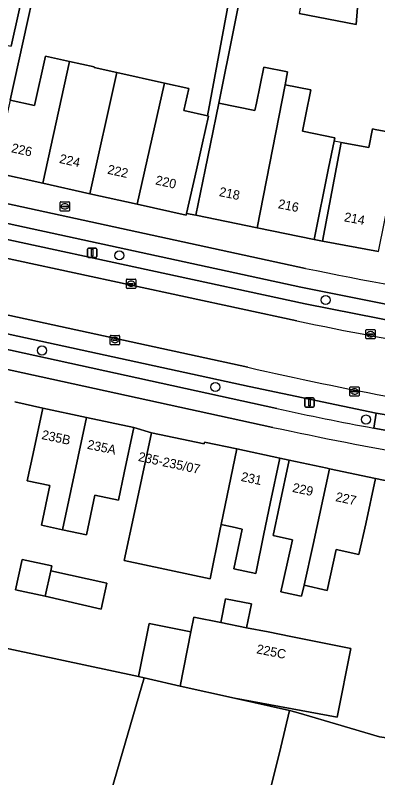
# Model space of a CAD drawing. Extents: x 158086 to 159499, y 382904 to 383981.
# Drawn here: x 158278.9 to 158318, y 383140.7 to 383222.9 of the extents above; entities that cross this region are included whole.
import ezdxf

# ---------------------------------------------------------------- set-up
doc = ezdxf.new("R2010")
doc.units = 0
for name, color, linetype in [('IMGEO_Berm_open', 7, 'Continuous'), ('IMGEO_Boom', 7, 'Continuous'), ('IMGEO_Brandkraan', 7, 'Continuous'), ('IMGEO_Erf', 7, 'Continuous'), ('IMGEO_Fietspad_gesloten', 7, 'Continuous'), ('IMGEO_Kolk', 7, 'Continuous'), ('IMGEO_Lichtmast', 7, 'Continuous'), ('IMGEO_Pand', 7, 'Continuous'), ('IMGEO_Pand_nummerreeks', 7, 'Continuous'), ('IMGEO_Pand_overbouw', 7, 'Continuous'), ('IMGEO_Parkeervlak_open', 7, 'Continuous'), ('IMGEO_Rijbaan_lokaal_gesloten', 7, 'Continuous'), ('IMGEO_Voetpad_open', 7, 'Continuous')]:
    doc.layers.add(name, color=color, linetype=linetype)

msp = doc.modelspace()

# ---------------------------------------------------------------- linework, layer by layer
at = {"layer": 'IMGEO_Berm_open'}
for points in [[(158276.869, 383198.965), (158310.165, 383191.768), (158320.914, 383189.662), (158321.216, 383191.287), (158309.726, 383193.572), (158241.35, 383208.396), (158202.859, 383217.005), (158187.053, 383220.294)], [(158254.9, 383193.55), (158236.292, 383197.608), (158201.626, 383205.353), (158201.292, 383203.669), (158307.14, 383180.487)], [(158304.134, 383182.846), (158274.722, 383189.241)], [(158317.563, 383178.385), (158317.844, 383179.993), (158304.134, 383182.846)]]:
    msp.add_lwpolyline(points, dxfattribs=at)
msp.add_arc((158363.133, 383431.241), 256.929, 257.41247, 259.78379, dxfattribs=at)
at = {"layer": 'IMGEO_Boom'}
for centre in [(158290.149, 383196.988), (158312.381, 383192.178), (158281.81, 383186.743), (158300.492, 383182.804), (158316.724, 383179.303)]:
    msp.add_circle(centre, 0.489, dxfattribs=at)
at = {"layer": 'IMGEO_Brandkraan'}
for p, q in [((158283.773, 383201.849), (158283.773, 383202.701)), ((158283.848, 383202.775), (158284.7, 383202.775)), ((158284.261, 383202.555), (158284.286, 383202.555)), ((158284.774, 383202.701), (158284.774, 383201.849)), ((158284.7, 383201.775), (158283.848, 383201.775)), ((158284.032, 383202.269), (158284.032, 383202.281)), ((158284.47, 383202.232), (158284.072, 383202.232)), ((158284.075, 383202.318), (158284.473, 383202.318)), ((158284.284, 383201.995), (158284.259, 383201.995)), ((158284.516, 383202.281), (158284.516, 383202.269))]:
    msp.add_line(p, q, dxfattribs=at)
for points in [[(158283.773, 383201.849), (158283.773, 383202.701)], [(158283.848, 383202.775), (158284.7, 383202.775)], [(158284.774, 383202.701), (158284.774, 383201.849)], [(158284.7, 383201.775), (158283.848, 383201.775)]]:
    msp.add_lwpolyline(points, dxfattribs=at)
for centre, radius, start, end in [((158283.85, 383202.699), 0.0765, 91.55205, 178.44795), ((158283.85, 383202.699), 0.0765, 91.55205, 178.44795), ((158284.698, 383202.699), 0.0765, 1.55205, 88.44795), ((158284.698, 383202.699), 0.0765, 1.55205, 88.44795), ((158283.85, 383201.851), 0.0765, 181.55205, 268.44795), ((158283.85, 383201.851), 0.0765, 181.55205, 268.44795), ((158284.072, 383202.278), 0.0403, 85.87752, 175.75265), ((158284.069, 383202.268), 0.0366, 178.93798, 274.71019), ((158284.473, 383202.275), 0.043, 264.86636, 352.45326), ((158284.477, 383202.28), 0.0386, 1.73085, 96.63898), ((158284.698, 383201.851), 0.0765, 271.55205, 358.44795), ((158284.698, 383201.851), 0.0765, 271.55205, 358.44795)]:
    msp.add_arc(centre, radius, start, end, dxfattribs=at)
for centre, major_axis, ratio, start_param, end_param in [((158284.26, 383202.275), (-0.387, 0.002), 0.722429, 4.712389, 7.853982), ((158284.285, 383202.275), (-0.39, 0.002), 0.717154, 1.570796, 4.712389)]:
    msp.add_ellipse(centre, major_axis=major_axis, ratio=ratio, start_param=start_param, end_param=end_param, dxfattribs=at)
at = {"layer": 'IMGEO_Erf'}
for points in [[(158283.383, 383241.47), (158276.191, 383243.15), (158275.131, 383238.484), (158270.865, 383239.454), (158270.731, 383238.86), (158264.911, 383240.184), (158260.691, 383221.367), (158263.775, 383220.678), (158265.351, 383227.737), (158267.873, 383227.174), (158267.293, 383224.576), (158269.747, 383224.028), (158269.199, 383221.573), (158267.997, 383216.19), (158271.563, 383215.394), (158272.77, 383220.82), (158278.489, 383219.543)], [(158303.246, 383231.413), (158298.621, 383232.637), (158298.105, 383230.685), (158293.201, 383231.983), (158293.24, 383232.149), (158288.16, 383233.26), (158287.893, 383232.039), (158282.666, 383233.182), (158278.387, 383213.724), (158281.013, 383213.138), (158282.206, 383218.481), (158284.791, 383217.904), (158287.429, 383217.315), (158287.418, 383217.261), (158289.866, 383216.714), (158295.004, 383215.566), (158297.637, 383214.977), (158297.109, 383212.609), (158299.661, 383212.039)], [(158282.865, 383163.519), (158282.749, 383162.993), (158288.817, 383161.655), (158288.197, 383158.842), (158282.146, 383160.259), (158278.959, 383160.961), (158279.678, 383164.222)]]:
    msp.add_lwpolyline(points, close=True, dxfattribs=at)
for points in [[(158316.527, 383232.939), (158315.687, 383221.879), (158309.526, 383223.074)], [(158304.128, 383229.734), (158300.88, 383213.391), (158304.765, 383212.596), (158304.927, 383213.388), (158305.728, 383217.298), (158308.277, 383216.776), (158308.009, 383215.395), (158310.801, 383214.823), (158310.262, 383212.193), (158309.888, 383210.368), (158313.372, 383209.654), (158313.302, 383209.314), (158312.706, 383206.404), (158311.132, 383198.719), (158312.044, 383198.541), (158314.046, 383209.174), (158317.047, 383208.608), (158317.427, 383210.63), (158317.709, 383210.577), (158320.635, 383210.026)], [(158322.217, 383172.026), (158317.747, 383172.943), (158316.704, 383168.053), (158315.955, 383164.754), (158313.526, 383165.288), (158312.556, 383160.881), (158310.053, 383161.432), (158309.793, 383160.248), (158309.561, 383160.299), (158307.566, 383160.738), (158307.807, 383161.835), (158308.797, 383166.329), (158306.711, 383166.788), (158307.404, 383170.036), (158308.447, 383174.926), (158307.439, 383175.141), (158306.396, 383170.252), (158305.738, 383166.996), (158304.849, 383162.702), (158302.48, 383163.207), (158303.395, 383167.499), (158302.324, 383167.727), (158301.254, 383167.955), (158301.132, 383167.981), (158300.995, 383167.31), (158299.938, 383162.145), (158290.677, 383164.118), (158291.78, 383169.292), (158292.569, 383172.995), (158293.612, 383177.885), (158291.71, 383178.432), (158290.668, 383173.542), (158290.043, 383170.612), (158287.507, 383171.153), (158286.596, 383166.878), (158284.04, 383167.423), (158281.758, 383167.91), (158282.669, 383172.18), (158280.23, 383172.701), (158280.856, 383175.635), (158281.898, 383180.525), (158278.879, 383181.201)], [(158272.796, 383155.743), (158292.196, 383151.584), (158293.362, 383157.32), (158297.853, 383156.407), (158298.171, 383158.005), (158301.092, 383157.42), (158301.606, 383159.987), (158304.376, 383159.432), (158303.861, 383156.865), (158306.179, 383156.4), (158308.629, 383155.909), (158315.091, 383154.614), (158313.609, 383147.219), (158302.551, 383149.261), (158308.489, 383147.926), (158309.179, 383147.771), (158310.039, 383147.519), (158313.464, 383146.515), (158318.204, 383145.101), (158345.406, 383141.19), (158345.597, 383141.163), (158347.51, 383148.249), (158355.692, 383146.915), (158351.159, 383130.728)]]:
    msp.add_lwpolyline(points, dxfattribs=at)
at = {"layer": 'IMGEO_Fietspad_gesloten'}
for points in [[(158310.224, 383195.595), (158241.603, 383210.483), (158207.946, 383218.002), (158195.608, 383220.653), (158184.729, 383222.86)], [(158187.053, 383220.294), (158202.859, 383217.005), (158241.35, 383208.396), (158309.726, 383193.572), (158321.216, 383191.287), (158327.206, 383190.282)], [(158138.36, 383212.086), (158139.992, 383211.926), (158163.458, 383208.795), (158169.284, 383207.897), (158174.364, 383207.03), (158187.059, 383204.599), (158306.699, 383178.457)], [(158307.14, 383180.487), (158201.292, 383203.669), (158197.351, 383204.538), (158190.588, 383205.987)], [(158323.581, 383177.291), (158317.563, 383178.385)]]:
    msp.add_lwpolyline(points, dxfattribs=at)
for centre, radius, start, end in [((158417.115, 383717.399), 532.64, 258.42313, 262.61206), ((158363.133, 383431.241), 256.929, 257.41247, 259.78379), ((158394.655, 383587.161), 418.061, 257.85472, 262.24316)]:
    msp.add_arc(centre, radius, start, end, dxfattribs=at)
at = {"layer": 'IMGEO_Kolk'}
for p, q in [((158290.913, 383193.513), (158290.913, 383194.365)), ((158290.988, 383194.439), (158291.84, 383194.439)), ((158291.914, 383194.365), (158291.914, 383193.513)), ((158291.172, 383193.933), (158291.172, 383193.945)), ((158291.61, 383193.896), (158291.212, 383193.896)), ((158291.215, 383193.982), (158291.613, 383193.982)), ((158291.424, 383193.659), (158291.399, 383193.659)), ((158291.401, 383194.219), (158291.426, 383194.219)), ((158291.656, 383193.945), (158291.656, 383193.933)), ((158291.84, 383193.439), (158290.988, 383193.439)), ((158316.718, 383188.07), (158316.718, 383188.922)), ((158316.793, 383188.996), (158317.645, 383188.996)), ((158317.206, 383188.776), (158317.231, 383188.776)), ((158317.719, 383188.922), (158317.719, 383188.07)), ((158289.177, 383187.44), (158289.177, 383188.292)), ((158289.252, 383188.366), (158290.104, 383188.366)), ((158289.436, 383187.86), (158289.436, 383187.872)), ((158289.874, 383187.823), (158289.476, 383187.823)), ((158289.479, 383187.909), (158289.877, 383187.909)), ((158289.665, 383188.146), (158289.69, 383188.146)), ((158289.92, 383187.872), (158289.92, 383187.86)), ((158290.178, 383188.292), (158290.178, 383187.44)), ((158317.645, 383187.996), (158316.793, 383187.996)), ((158316.977, 383188.49), (158316.977, 383188.502)), ((158317.415, 383188.453), (158317.017, 383188.453)), ((158317.02, 383188.539), (158317.418, 383188.539)), ((158317.229, 383188.216), (158317.204, 383188.216)), ((158317.461, 383188.502), (158317.461, 383188.49)), ((158290.104, 383187.366), (158289.252, 383187.366)), ((158289.688, 383187.586), (158289.663, 383187.586)), ((158315.066, 383182.823), (158315.918, 383182.823)), ((158314.991, 383181.897), (158314.991, 383182.749)), ((158315.25, 383182.317), (158315.25, 383182.329)), ((158315.688, 383182.28), (158315.29, 383182.28)), ((158315.293, 383182.366), (158315.691, 383182.366)), ((158315.502, 383182.043), (158315.477, 383182.043)), ((158315.479, 383182.603), (158315.504, 383182.603)), ((158315.734, 383182.329), (158315.734, 383182.317)), ((158315.992, 383182.749), (158315.992, 383181.897)), ((158315.918, 383181.823), (158315.066, 383181.823))]:
    msp.add_line(p, q, dxfattribs=at)
for points in [[(158290.913, 383193.513), (158290.913, 383194.365)], [(158290.988, 383194.439), (158291.84, 383194.439)], [(158291.914, 383194.365), (158291.914, 383193.513)], [(158291.84, 383193.439), (158290.988, 383193.439)], [(158316.718, 383188.07), (158316.718, 383188.922)], [(158316.793, 383188.996), (158317.645, 383188.996)], [(158317.719, 383188.922), (158317.719, 383188.07)], [(158289.177, 383187.44), (158289.177, 383188.292)], [(158289.252, 383188.366), (158290.104, 383188.366)], [(158290.178, 383188.292), (158290.178, 383187.44)], [(158317.645, 383187.996), (158316.793, 383187.996)], [(158290.104, 383187.366), (158289.252, 383187.366)], [(158315.066, 383182.823), (158315.918, 383182.823)], [(158314.991, 383181.897), (158314.991, 383182.749)], [(158315.992, 383182.749), (158315.992, 383181.897)], [(158315.918, 383181.823), (158315.066, 383181.823)]]:
    msp.add_lwpolyline(points, dxfattribs=at)
for centre, radius, start, end in [((158290.99, 383194.363), 0.0765, 91.55205, 178.44795), ((158290.99, 383194.363), 0.0765, 91.55205, 178.44795), ((158291.838, 383194.363), 0.0765, 1.55205, 88.44795), ((158291.838, 383194.363), 0.0765, 1.55205, 88.44795), ((158290.99, 383193.515), 0.0765, 181.55205, 268.44795), ((158290.99, 383193.515), 0.0765, 181.55205, 268.44795), ((158291.212, 383193.942), 0.0403, 85.87752, 175.75265), ((158291.209, 383193.932), 0.0366, 178.93798, 274.71019), ((158291.613, 383193.939), 0.043, 264.86636, 352.45326), ((158291.617, 383193.944), 0.0386, 1.73085, 96.63898), ((158291.838, 383193.515), 0.0765, 271.55205, 358.44795), ((158291.838, 383193.515), 0.0765, 271.55205, 358.44795), ((158316.795, 383188.92), 0.0765, 91.55205, 178.44795), ((158316.795, 383188.92), 0.0765, 91.55205, 178.44795), ((158317.643, 383188.92), 0.0765, 1.55205, 88.44795), ((158317.643, 383188.92), 0.0765, 1.55205, 88.44795), ((158289.254, 383188.29), 0.0765, 91.55205, 178.44795), ((158289.254, 383188.29), 0.0765, 91.55205, 178.44795), ((158289.476, 383187.869), 0.0403, 85.87752, 175.75265), ((158289.473, 383187.859), 0.0366, 178.93798, 274.71019), ((158289.877, 383187.866), 0.043, 264.86636, 352.45326), ((158289.881, 383187.871), 0.0386, 1.73085, 96.63898), ((158290.102, 383188.29), 0.0765, 1.55205, 88.44795), ((158290.102, 383188.29), 0.0765, 1.55205, 88.44795), ((158316.795, 383188.072), 0.0765, 181.55205, 268.44795), ((158316.795, 383188.072), 0.0765, 181.55205, 268.44795), ((158317.017, 383188.499), 0.0403, 85.87752, 175.75265), ((158317.014, 383188.489), 0.0366, 178.93798, 274.71019), ((158317.418, 383188.496), 0.043, 264.86636, 352.45326), ((158317.422, 383188.501), 0.0386, 1.73085, 96.63898), ((158317.643, 383188.072), 0.0765, 271.55205, 358.44795), ((158317.643, 383188.072), 0.0765, 271.55205, 358.44795), ((158289.254, 383187.442), 0.0765, 181.55205, 268.44795), ((158289.254, 383187.442), 0.0765, 181.55205, 268.44795), ((158290.102, 383187.442), 0.0765, 271.55205, 358.44795), ((158290.102, 383187.442), 0.0765, 271.55205, 358.44795), ((158315.068, 383182.747), 0.0765, 91.55205, 178.44795), ((158315.068, 383182.747), 0.0765, 91.55205, 178.44795), ((158315.916, 383182.747), 0.0765, 1.55205, 88.44795), ((158315.916, 383182.747), 0.0765, 1.55205, 88.44795), ((158315.29, 383182.326), 0.0403, 85.87752, 175.75265), ((158315.287, 383182.316), 0.0366, 178.93798, 274.71019), ((158315.691, 383182.323), 0.043, 264.86636, 352.45326), ((158315.695, 383182.328), 0.0386, 1.73085, 96.63898), ((158315.068, 383181.899), 0.0765, 181.55205, 268.44795), ((158315.068, 383181.899), 0.0765, 181.55205, 268.44795), ((158315.916, 383181.899), 0.0765, 271.55205, 358.44795), ((158315.916, 383181.899), 0.0765, 271.55205, 358.44795)]:
    msp.add_arc(centre, radius, start, end, dxfattribs=at)
for centre, major_axis, ratio, start_param, end_param in [((158291.4, 383193.939), (-0.387, 0.002), 0.722429, 4.712389, 7.853982), ((158291.425, 383193.939), (-0.39, 0.002), 0.717154, 1.570796, 4.712389), ((158317.205, 383188.496), (-0.387, 0.002), 0.722429, 4.712389, 7.853982), ((158317.23, 383188.496), (-0.39, 0.002), 0.717154, 1.570796, 4.712389), ((158289.664, 383187.866), (-0.387, 0.002), 0.722429, 4.712389, 7.853982), ((158289.689, 383187.866), (-0.39, 0.002), 0.717154, 1.570796, 4.712389), ((158315.478, 383182.323), (-0.387, 0.002), 0.722429, 4.712389, 7.853982), ((158315.503, 383182.323), (-0.39, 0.002), 0.717154, 1.570796, 4.712389)]:
    msp.add_ellipse(centre, major_axis=major_axis, ratio=ratio, start_param=start_param, end_param=end_param, dxfattribs=at)
at = {"layer": 'IMGEO_Lichtmast'}
for p, q in [((158286.723, 383196.876), (158286.723, 383197.676)), ((158286.723, 383197.676), (158286.723, 383196.876)), ((158286.823, 383197.776), (158287.613, 383197.776)), ((158287.613, 383197.776), (158286.823, 383197.776)), ((158287.713, 383197.676), (158287.713, 383196.876)), ((158287.713, 383196.876), (158287.713, 383197.676)), ((158287.613, 383196.776), (158286.823, 383196.776)), ((158286.823, 383196.776), (158287.613, 383196.776)), ((158310.14, 383180.745), (158310.14, 383181.545)), ((158310.14, 383181.545), (158310.14, 383180.745)), ((158310.24, 383181.645), (158311.03, 383181.645)), ((158311.03, 383181.645), (158310.24, 383181.645)), ((158311.13, 383181.545), (158311.13, 383180.745)), ((158311.13, 383180.745), (158311.13, 383181.545)), ((158311.03, 383180.645), (158310.24, 383180.645)), ((158310.24, 383180.645), (158311.03, 383180.645))]:
    msp.add_line(p, q, dxfattribs=at)
for points in [[(158287.143, 383197.651), (158287.293, 383197.651), (158287.293, 383196.901), (158287.143, 383196.901), (158287.143, 383197.651)], [(158310.56, 383181.52), (158310.71, 383181.52), (158310.71, 383180.77), (158310.56, 383180.77), (158310.56, 383181.52)]]:
    msp.add_lwpolyline(points, dxfattribs=at)
for centre, start, end in [((158286.823, 383197.676), 90, 180), ((158286.823, 383197.676), 90, 180), ((158287.613, 383197.676), 0, 90), ((158287.613, 383197.676), 360, 90), ((158286.823, 383196.876), 180, 270), ((158286.823, 383196.876), 180, 270), ((158287.613, 383196.876), 270, 0), ((158287.613, 383196.876), 270, 0), ((158310.24, 383181.545), 90, 180), ((158310.24, 383181.545), 90, 180), ((158311.03, 383181.545), 0, 90), ((158311.03, 383181.545), 360, 90), ((158310.24, 383180.745), 180, 270), ((158310.24, 383180.745), 180, 270), ((158311.03, 383180.745), 270, 0), ((158311.03, 383180.745), 270, 0)]:
    msp.add_arc(centre, 0.1, start, end, dxfattribs=at)
at = {"layer": 'IMGEO_Pand'}
for points in [[(158316.527, 383232.939), (158311.633, 383234.07), (158310.525, 383228.36), (158309.526, 383223.074), (158315.687, 383221.879)], [(158284.791, 383217.904), (158282.206, 383218.481), (158281.013, 383213.138), (158278.387, 383213.724), (158277.74, 383210.824), (158276.65, 383205.944), (158281.908, 383204.77)], [(158289.866, 383216.714), (158287.418, 383217.261), (158287.429, 383217.315), (158284.791, 383217.904), (158281.908, 383204.77), (158286.976, 383203.639)], [(158295.004, 383215.566), (158289.866, 383216.714), (158286.976, 383203.639), (158292.066, 383202.503), (158294.967, 383215.402)], [(158308.009, 383215.395), (158308.277, 383216.776), (158305.728, 383217.298), (158304.927, 383213.388), (158304.765, 383212.596), (158300.88, 383213.391), (158299.985, 383209.022), (158299.412, 383206.225), (158298.408, 383201.326), (158305.016, 383199.972)], [(158299.1, 383209.119), (158299.747, 383212.02), (158299.661, 383212.039), (158297.109, 383212.609), (158297.637, 383214.977), (158295.004, 383215.566), (158294.967, 383215.402), (158292.066, 383202.503), (158297.359, 383201.321), (158297.405, 383201.528), (158298.449, 383206.201)], [(158313.302, 383209.314), (158313.372, 383209.654), (158309.888, 383210.368), (158310.262, 383212.193), (158310.801, 383214.823), (158308.009, 383215.395), (158305.016, 383199.972), (158311.132, 383198.719), (158312.706, 383206.404)], [(158320.635, 383210.026), (158317.709, 383210.577), (158317.427, 383210.63), (158317.047, 383208.608), (158314.046, 383209.174), (158312.044, 383198.541), (158318.089, 383197.403)], [(158284.04, 383167.423), (158286.621, 383179.518), (158281.898, 383180.525), (158280.856, 383175.635), (158280.23, 383172.701), (158282.669, 383172.18), (158281.758, 383167.91)], [(158284.04, 383167.423), (158286.596, 383166.878), (158287.507, 383171.153), (158290.043, 383170.612), (158290.668, 383173.542), (158291.71, 383178.432), (158286.621, 383179.518)], [(158302.8, 383176.13), (158299.321, 383176.872), (158299.279, 383176.676), (158293.612, 383177.885), (158292.569, 383172.995), (158291.78, 383169.292), (158290.677, 383164.118), (158299.938, 383162.145), (158300.995, 383167.31), (158301.132, 383167.981)], [(158307.439, 383175.141), (158302.8, 383176.13), (158301.132, 383167.981), (158301.254, 383167.955), (158302.324, 383167.727), (158303.395, 383167.499), (158302.48, 383163.207), (158304.849, 383162.702), (158305.738, 383166.996), (158306.396, 383170.252)], [(158312.818, 383173.994), (158312.553, 383174.05), (158308.447, 383174.926), (158307.404, 383170.036), (158306.711, 383166.788), (158308.797, 383166.329), (158307.807, 383161.835), (158307.566, 383160.738), (158309.561, 383160.299), (158309.793, 383160.248), (158310.053, 383161.432), (158311.023, 383165.839)], [(158317.747, 383172.943), (158312.818, 383173.994), (158311.023, 383165.839), (158310.053, 383161.432), (158312.556, 383160.881), (158313.526, 383165.288), (158315.955, 383164.754), (158316.704, 383168.053)], [(158282.749, 383162.993), (158282.865, 383163.519), (158279.678, 383164.222), (158278.959, 383160.961), (158282.146, 383160.259)], [(158282.749, 383162.993), (158282.146, 383160.259), (158288.197, 383158.842), (158288.817, 383161.655)], [(158301.092, 383157.42), (158303.861, 383156.865), (158304.376, 383159.432), (158301.606, 383159.987)], [(158315.091, 383154.614), (158308.629, 383155.909), (158306.179, 383156.4), (158303.861, 383156.865), (158301.092, 383157.42), (158298.171, 383158.005), (158297.853, 383156.407), (158296.695, 383150.577), (158302.551, 383149.261), (158313.609, 383147.219)], [(158297.853, 383156.407), (158293.362, 383157.32), (158292.196, 383151.584), (158292.83, 383151.446), (158293.277, 383151.345), (158296.695, 383150.577)], [(158292.83, 383151.446), (158292.196, 383151.584), (158272.796, 383155.743), (158271.142, 383150.234), (158268.534, 383142.116), (158263.755, 383126.193), (158283.733, 383120.195)], [(158307.558, 383143.998), (158308.489, 383147.926), (158302.551, 383149.261), (158296.695, 383150.577), (158293.277, 383151.345), (158292.83, 383151.446), (158283.733, 383120.195), (158292.701, 383117.502), (158293.075, 383118.749), (158298.822, 383117.024), (158298.448, 383115.777), (158299.97, 383115.32), (158299.992, 383115.395), (158302.582, 383124.02)], [(158302.582, 383124.02), (158307.351, 383122.714), (158312.028, 383121.434), (158322.301, 383118.595), (158320.048, 383110.442), (158320.519, 383110.313), (158330.348, 383107.621), (158330.464, 383108.046), (158328.778, 383108.509), (158329.66, 383111.73), (158331.346, 383111.267), (158332.575, 383115.755), (158338.235, 383114.205), (158343.493, 383134.04), (158345.406, 383141.19), (158318.204, 383145.101), (158313.464, 383146.515), (158310.039, 383147.519), (158309.179, 383147.771), (158308.489, 383147.926), (158307.558, 383143.998)]]:
    msp.add_lwpolyline(points, close=True, dxfattribs=at)
at = {"layer": 'IMGEO_Pand_overbouw'}
msp.add_lwpolyline([(158313.302, 383209.314), (158312.706, 383206.404), (158311.132, 383198.719), (158312.044, 383198.541), (158314.046, 383209.174)], close=True, dxfattribs=at)
at = {"layer": 'IMGEO_Parkeervlak_open'}
for points in [[(158326.927, 383188.643), (158320.914, 383189.662), (158310.165, 383191.768), (158276.869, 383198.965)], [(158273.257, 383197.701), (158309.28, 383189.934)], [(158304.012, 383184.929), (158272.028, 383191.873)], [(158274.722, 383189.241), (158304.134, 383182.846), (158317.844, 383179.993), (158323.83, 383178.975)]]:
    msp.add_lwpolyline(points, dxfattribs=at)
for centre, radius, start, end in [((158410.997, 383679.874), 500.387, 258.27133, 262.03898), ((158386.44, 383543.911), 368.324, 257.06812, 262.13031)]:
    msp.add_arc(centre, radius, start, end, dxfattribs=at)
at = {"layer": 'IMGEO_Rijbaan_lokaal_gesloten'}
msp.add_lwpolyline([(158309.28, 383189.934), (158273.257, 383197.701), (158272.028, 383191.873), (158304.012, 383184.929)], dxfattribs=at)
for centre, radius, start, end in [((158410.997, 383679.874), 500.387, 258.27133, 262.03898), ((158386.44, 383543.911), 368.324, 257.06812, 262.13031)]:
    msp.add_arc(centre, radius, start, end, dxfattribs=at)
at = {"layer": 'IMGEO_Voetpad_open'}
for points in [[(158276.191, 383243.15), (158283.383, 383241.47), (158278.489, 383219.543)], [(158278.387, 383213.724), (158282.666, 383233.182)], [(158184.729, 383222.86), (158195.608, 383220.653), (158207.946, 383218.002), (158241.603, 383210.483), (158310.224, 383195.595)], [(158318.089, 383197.403), (158312.044, 383198.541), (158311.132, 383198.719), (158305.016, 383199.972), (158298.408, 383201.326), (158297.405, 383201.528), (158297.359, 383201.321), (158292.066, 383202.503), (158286.976, 383203.639), (158281.908, 383204.77), (158276.65, 383205.944)], [(158306.699, 383178.457), (158187.059, 383204.599)], [(158278.879, 383181.201), (158281.898, 383180.525), (158286.621, 383179.518), (158291.71, 383178.432), (158293.612, 383177.885), (158299.279, 383176.676), (158299.321, 383176.872), (158302.8, 383176.13), (158307.439, 383175.141), (158308.447, 383174.926), (158312.553, 383174.05), (158312.818, 383173.994), (158317.747, 383172.943), (158322.217, 383172.026), (158328.791, 383171.091), (158335.048, 383170.201), (158341.316, 383169.31), (158347.41, 383168.443), (158352.008, 383167.806), (158357.974, 383167.163), (158360.405, 383166.88), (158365.71, 383166.399), (158371.528, 383165.871), (158436.17, 383162.405)]]:
    msp.add_lwpolyline(points, dxfattribs=at)
for points in [[(158300.88, 383213.391), (158304.128, 383229.734), (158305.417, 383235.738), (158299.81, 383237.129), (158299.521, 383236.036), (158304.145, 383234.812), (158303.246, 383231.413), (158299.661, 383212.039), (158299.747, 383212.02), (158299.1, 383209.119), (158298.449, 383206.201), (158297.405, 383201.528), (158298.408, 383201.326), (158299.412, 383206.225), (158299.985, 383209.022)], [(158323.83, 383178.975), (158317.844, 383179.993), (158317.563, 383178.385), (158323.581, 383177.291)]]:
    msp.add_lwpolyline(points, close=True, dxfattribs=at)
for centre, radius, start, end in [((158417.115, 383717.399), 532.64, 258.42313, 262.61206), ((158394.655, 383587.161), 418.061, 257.85472, 262.24316)]:
    msp.add_arc(centre, radius, start, end, dxfattribs=at)

# ---------------------------------------------------------------- texts
at = {"layer": 'IMGEO_Pand_nummerreeks'}
for s, rotation, p in [('226', 347.41785, (158278.443, 383208.125)), ('224', 347.41785, (158283.621, 383206.97)), ('222', 347.41785, (158288.795, 383205.815)), ('220', 347.41785, (158293.978, 383204.658)), ('218', 348.42052, (158300.837, 383203.401)), ('216', 348.42052, (158307.195, 383202.098)), ('214', 349.34299, (158314.314, 383200.678)), ('235B', 347.96408, (158281.71, 383177.211)), ('235A', 347.95369, (158286.615, 383176.165)), ('235-235/07', 347.90486, (158292.12, 383174.85)), ('231', 347.96789, (158303.198, 383172.691)), ('229', 347.96216, (158308.74, 383171.51)), ('227', 347.96216, (158313.39, 383170.519)), ('225C', 348.66689, (158304.869, 383154.113))]:
    msp.add_text(s, height=1, rotation=rotation, dxfattribs=at).set_placement(p)

doc.saveas('drawing.dxf')
